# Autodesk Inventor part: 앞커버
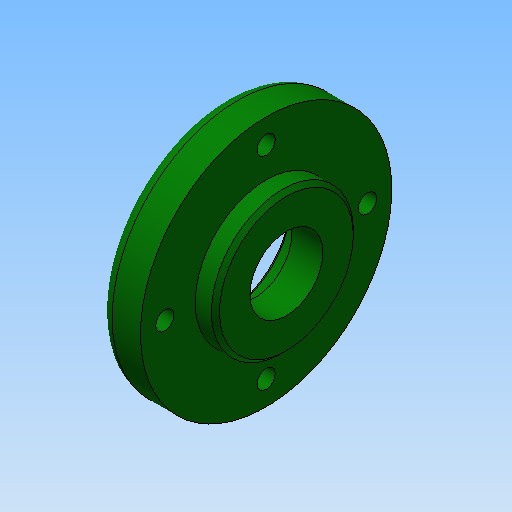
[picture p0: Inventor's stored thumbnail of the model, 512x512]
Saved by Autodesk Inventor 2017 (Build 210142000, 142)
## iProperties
Created: 2015-12
Part Number: 앞커버
Document SubType Name: Modeling
Designer: mdu
Density: 2.71 g/cm^3
Material: 알루미늄 6061
Appearance: 진녹색
Author: mdu
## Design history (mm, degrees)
sketch "스케치1"
  geometry: L1 (-7.5, 0)-(7.5, 0); L2 (-7.5, 0)-(-7.5, 31); L3 (-7.5, 31)-(2.5, 31); L4 (2.5, 31)-(2.5, 17.5); L5 (2.5, 17.5)-(7.5, 17.5); L6 (7.5, 17.5)-(7.5, 0); 2 further points
  constraints: 12 end point, 3 perpendicular, 1 coincident, 1 horizontal, 1 midpoint, 1 parallel
  dimensions: "d0" = 15 distance of L1.start L1.end; "d1" = 62 diameter of L3 L1; "d2" = 35 diameter of L5 L1; "d5" = 10 distance of L2.end L3.end
revolve "회전1" sketch "스케치1" stored, may be unused: angle "d6" = 90 deg
sketch "스케치2" dims "d42" = 50
  geometry: 3 further points
  constraints: 2 vertical alignment, 1 coincident, 2 other
hole "구멍1" sketch "스케치2" at (0, 25) diameter "d8" = 4.5; stored, may be unused: countersink angle "d12" = 90 deg, drill point angle "d14" = 118 deg; dims "d9" = 6, "d10" = 8, "d11" = 4.4, "d13" = 8
hole "구멍2" diameter "d20" = 18; stored, may be unused: countersink angle "d24" = 90 deg, drill point angle "d26" = 0 deg; dims "d18" = 10, "d19" = 10, "d21" = 6, "d22" = 8, "d23" = 4.4, "d25" = 8
hole "구멍3" diameter "d34" = 30; stored, may be unused: countersink angle "d38" = 90 deg, drill point angle "d40" = 0 deg; dims "d32" = 10, "d33" = 10, "d35" = 6, "d36" = 4, "d37" = 2, "d39" = 7.3
fillet "모깎기1" dims "d27" = 3, "d41" = 0.3
chamfer "모따기1" distance "d29" = 1; stored, may be unused: second distance "d30" = 2, angle "d31" = 45 deg
node "솔리드1"
pattern_circular "원형 패턴1" dims angle "d16" = 360 deg
